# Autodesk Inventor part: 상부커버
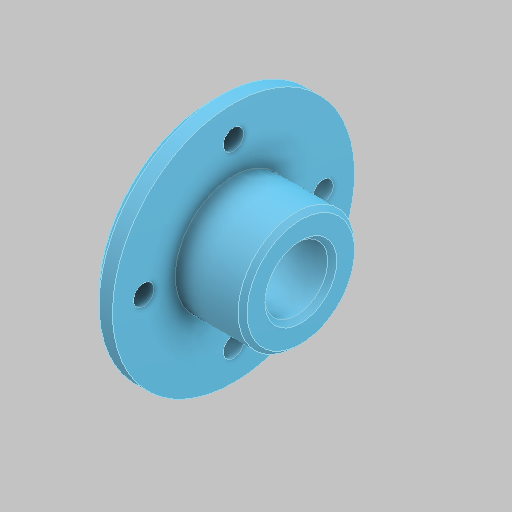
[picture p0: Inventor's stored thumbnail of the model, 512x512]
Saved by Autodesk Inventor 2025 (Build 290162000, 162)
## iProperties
Created: 2024-07
Part Number: 상부커버
Material: 알루미늄 6061
Document SubType Name: Modeling
Designer: 현기
Density: 2.71 g/cm^3
Appearance: 기본값
Author: jhkim
Sending System: Autodesk Inventor 2025
Preprocessor: ST-DEVELOPER v20
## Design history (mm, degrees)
feature "솔리드1"
node "솔리드2"
